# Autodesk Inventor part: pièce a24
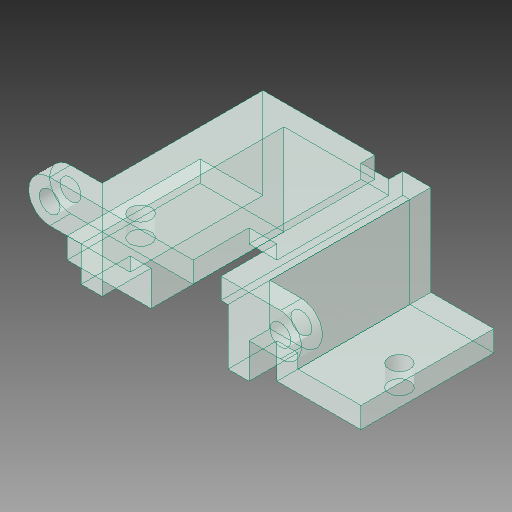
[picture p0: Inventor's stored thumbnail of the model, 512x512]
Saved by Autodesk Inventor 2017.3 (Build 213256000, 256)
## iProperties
Created: 2007-12
Part Number: pièce a24
Material: solidworks materials|PVC 0.007 plastifié|45
Document SubType Name: Modeling
Designer: ficho
Density: 1.29 g/cm^3
Appearance: 239,255,251
Author: ficho
Sending System: SolidWorks 2009
Last Author: christophe
Last Saved: 2011-02-10
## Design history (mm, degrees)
feature "Enlèv. mat.-Extru.6"
node "Solide1"
